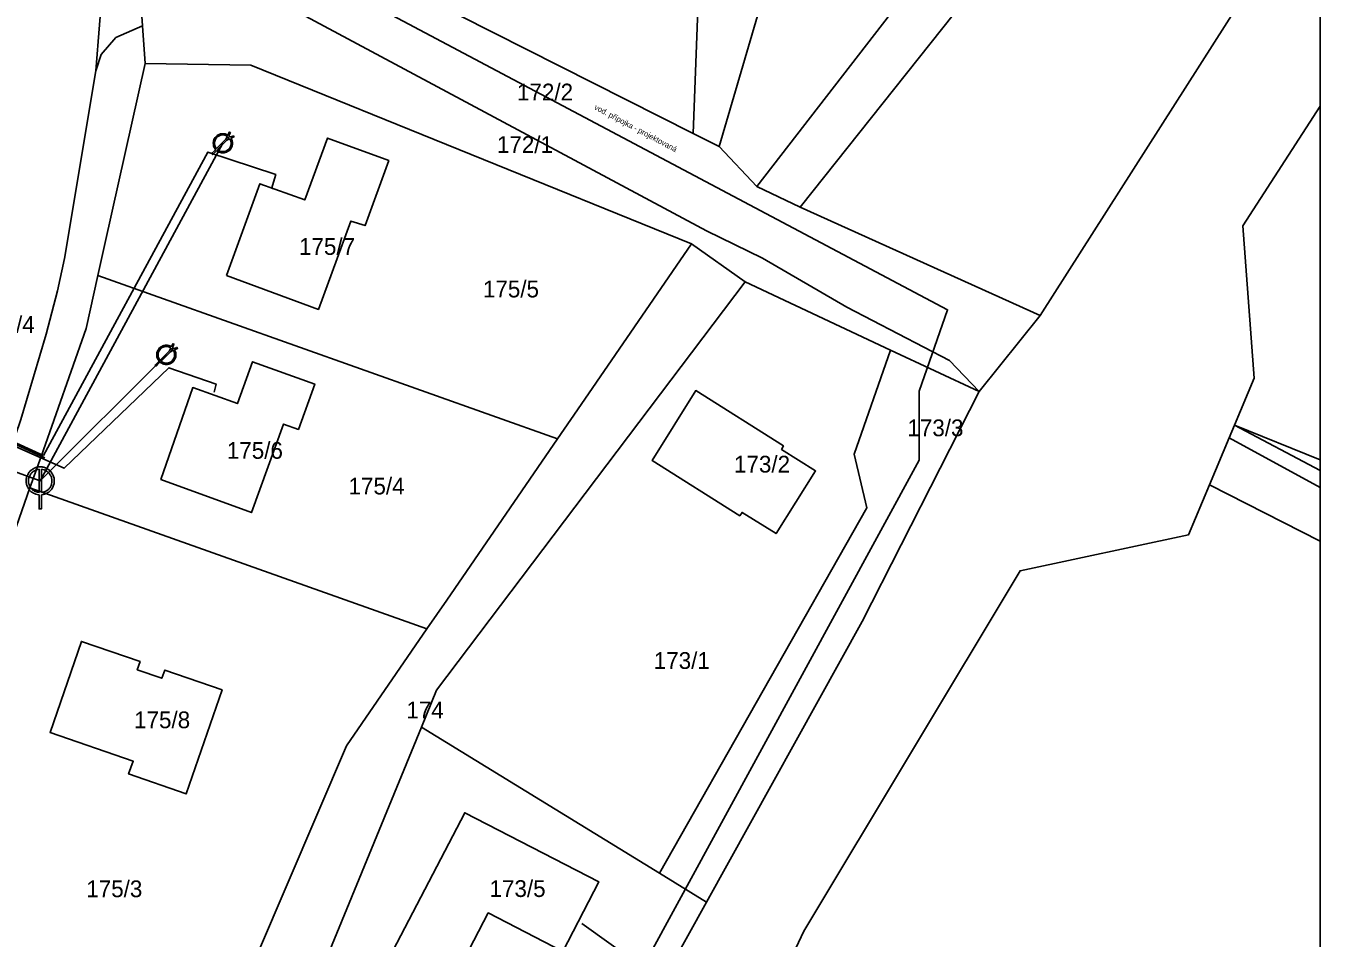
# Model space of a CAD drawing. Extents: x -559956 to -559707, y -1077221 to -1076919.
# Drawn here: x -559822.9 to -559707, y -1077119.6 to -1077037.9 of the extents above; entities that cross this region are included whole.
import ezdxf

# ---------------------------------------------------------------- set-up
doc = ezdxf.new("R2010")
doc.units = 0
for name, color, linetype in [('Chránička', 7, 'Continuous'), ('Doplňkový popis - vodovod', 7, 'Continuous'), ('Kanalizační přípojka', 7, 'Continuous'), ('Kanalizační šachta', 7, 'Continuous'), ('Odběrné místo na kanalizaci', 7, 'Continuous'), ('Parcela-polygon', 7, 'Continuous'), ('Parcela-text', 7, 'Continuous'), ('Vodovodní přípojka', 7, 'Continuous')]:
    doc.layers.add(name, color=color, linetype=linetype)

msp = doc.modelspace()

# ---------------------------------------------------------------- linework, layer by layer
at = {"layer": 'Chránička'}
msp.add_line((-559830.03, -1077072.56), (-559821.17, -1077076.58), dxfattribs=at)
at = {"layer": 'Kanalizační přípojka'}
msp.add_line((-559810.28, -1077067.37), (-559821.57, -1077078.65), dxfattribs=at)
msp.add_lwpolyline([(-559805.23, -1077048.44), (-559821.57, -1077078.65), (-559834.68, -1077073.91)], dxfattribs=at)
at = {"layer": 'Kanalizační šachta'}
for points in [[(-559821.67, -1077079.68), (-559821.67, -1077077.61)], [(-559821.47, -1077077.61), (-559821.47, -1077079.68)], [(-559821.47, -1077079.9), (-559821.47, -1077081.15), (-559821.67, -1077081.15), (-559821.67, -1077079.9)]]:
    msp.add_lwpolyline(points, dxfattribs=at)
for points in [[(-559821.67, -1077079.9), (-559821.93, -1077079.88), (-559822.19, -1077079.73), (-559822.49, -1077079.57), (-559822.65, -1077079.27), (-559822.82, -1077078.97), (-559822.82, -1077078.65), (-559822.82, -1077078.32), (-559822.65, -1077078.02), (-559822.48, -1077077.72), (-559822.18, -1077077.56), (-559821.89, -1077077.4), (-559821.57, -1077077.4), (-559821.25, -1077077.4), (-559820.95, -1077077.56), (-559820.66, -1077077.72), (-559820.49, -1077078.02), (-559820.32, -1077078.32), (-559820.32, -1077078.65), (-559820.32, -1077078.97), (-559820.48, -1077079.27), (-559820.65, -1077079.57), (-559820.95, -1077079.73), (-559821.21, -1077079.88), (-559821.47, -1077079.9)], [(-559821.67, -1077077.61), (-559821.87, -1077077.63), (-559822.08, -1077077.74), (-559822.33, -1077077.88), (-559822.47, -1077078.13), (-559822.61, -1077078.38), (-559822.61, -1077078.65), (-559822.61, -1077078.92), (-559822.47, -1077079.17), (-559822.34, -1077079.41), (-559822.09, -1077079.55), (-559821.88, -1077079.67), (-559821.67, -1077079.68)], [(-559821.47, -1077079.68), (-559821.26, -1077079.67), (-559821.05, -1077079.55), (-559820.8, -1077079.41), (-559820.66, -1077079.17), (-559820.53, -1077078.92), (-559820.53, -1077078.65), (-559820.53, -1077078.38), (-559820.67, -1077078.13), (-559820.81, -1077077.88), (-559821.06, -1077077.74), (-559821.27, -1077077.63), (-559821.47, -1077077.61)]]:
    msp.add_open_spline(points, degree=3, dxfattribs=at)
at = {"layer": 'Odběrné místo na kanalizaci'}
for points in [[(-559805.8, -1077048.91), (-559804.95, -1077048.07), (-559804.82, -1077047.81)], [(-559804.61, -1077048.03), (-559804.87, -1077048.16), (-559805.71, -1077049)], [(-559804.73, -1077047.88), (-559804.78, -1077047.98), (-559804.68, -1077047.93)], [(-559804.77, -1077047.71), (-559804.76, -1077047.69), (-559804.71, -1077047.58), (-559804.65, -1077047.44), (-559804.55, -1077047.48), (-559804.62, -1077047.64), (-559804.67, -1077047.76), (-559804.68, -1077047.78)], [(-559804.57, -1077047.88), (-559804.56, -1077047.87), (-559804.43, -1077047.83), (-559804.28, -1077047.77), (-559804.23, -1077047.86), (-559804.37, -1077047.92), (-559804.49, -1077047.97), (-559804.51, -1077047.98)], [(-559805.79, -1077049.08), (-559805.8, -1077049.1), (-559805.89, -1077049.19), (-559806.14, -1077049.44), (-559806.23, -1077049.35), (-559805.98, -1077049.1), (-559805.89, -1077049.01), (-559805.88, -1077049)], [(-559810.85, -1077067.85), (-559810.01, -1077067), (-559809.88, -1077066.75)], [(-559809.83, -1077066.65), (-559809.82, -1077066.63), (-559809.77, -1077066.51), (-559809.71, -1077066.37), (-559809.61, -1077066.41), (-559809.67, -1077066.58), (-559809.72, -1077066.7), (-559809.73, -1077066.71)], [(-559809.78, -1077066.82), (-559809.83, -1077066.92), (-559809.73, -1077066.87)], [(-559809.63, -1077066.82), (-559809.61, -1077066.81), (-559809.49, -1077066.76), (-559809.34, -1077066.7), (-559809.28, -1077066.79), (-559809.43, -1077066.85), (-559809.54, -1077066.9), (-559809.56, -1077066.91)], [(-559810.84, -1077068.02), (-559810.86, -1077068.03), (-559810.95, -1077068.12), (-559811.2, -1077068.37), (-559811.29, -1077068.28), (-559811.03, -1077068.03), (-559810.94, -1077067.94), (-559810.93, -1077067.93)], [(-559809.66, -1077066.96), (-559809.92, -1077067.09), (-559810.76, -1077067.94)]]:
    msp.add_lwpolyline(points, dxfattribs=at)
for points, degree in [([(-559805.88, -1077049), (-559805.93, -1077048.93), (-559805.97, -1077048.86), (-559806.08, -1077048.66), (-559806.08, -1077048.44), (-559806.08, -1077048.21), (-559805.97, -1077048.01), (-559805.85, -1077047.8), (-559805.65, -1077047.69), (-559805.44, -1077047.58), (-559805.23, -1077047.58), (-559805.01, -1077047.58), (-559804.81, -1077047.69), (-559804.79, -1077047.7), (-559804.77, -1077047.71)], 3), ([(-559804.82, -1077047.81), (-559804.84, -1077047.8), (-559804.86, -1077047.79), (-559805.04, -1077047.69), (-559805.23, -1077047.69), (-559805.42, -1077047.69), (-559805.59, -1077047.79), (-559805.77, -1077047.88), (-559805.87, -1077048.06), (-559805.97, -1077048.24), (-559805.97, -1077048.44), (-559805.97, -1077048.63), (-559805.87, -1077048.8), (-559805.84, -1077048.86), (-559805.8, -1077048.91)], 3), ([(-559804.51, -1077047.98), (-559804.5, -1077047.99), (-559804.49, -1077048.01), (-559804.37, -1077048.21), (-559804.37, -1077048.44), (-559804.37, -1077048.66), (-559804.49, -1077048.86), (-559804.6, -1077049.06), (-559804.8, -1077049.18), (-559805.01, -1077049.29), (-559805.23, -1077049.29), (-559805.45, -1077049.29), (-559805.65, -1077049.18), (-559805.73, -1077049.14), (-559805.79, -1077049.08)], 3), ([(-559805.71, -1077049), (-559805.66, -1077049.05), (-559805.6, -1077049.08), (-559805.42, -1077049.18), (-559805.23, -1077049.18), (-559805.04, -1077049.18), (-559804.86, -1077049.08), (-559804.68, -1077048.98), (-559804.58, -1077048.8), (-559804.49, -1077048.63), (-559804.49, -1077048.44), (-559804.49, -1077048.24), (-559804.58, -1077048.06), (-559804.6, -1077048.04), (-559804.61, -1077048.03)], 3), ([(-559804.68, -1077047.93), (-559804.7, -1077047.91), (-559804.73, -1077047.88)], 2), ([(-559804.68, -1077047.78), (-559804.62, -1077047.83), (-559804.57, -1077047.88)], 2), ([(-559810.93, -1077067.93), (-559810.98, -1077067.87), (-559811.02, -1077067.79), (-559811.14, -1077067.59), (-559811.14, -1077067.37), (-559811.14, -1077067.15), (-559811.02, -1077066.94), (-559810.91, -1077066.73), (-559810.7, -1077066.62), (-559810.5, -1077066.51), (-559810.28, -1077066.51), (-559810.07, -1077066.51), (-559809.86, -1077066.62), (-559809.84, -1077066.63), (-559809.83, -1077066.65)], 3), ([(-559809.88, -1077066.75), (-559809.9, -1077066.73), (-559809.92, -1077066.72), (-559810.1, -1077066.63), (-559810.28, -1077066.63), (-559810.47, -1077066.63), (-559810.65, -1077066.72), (-559810.83, -1077066.82), (-559810.93, -1077067), (-559811.02, -1077067.17), (-559811.02, -1077067.37), (-559811.02, -1077067.56), (-559810.93, -1077067.74), (-559810.89, -1077067.8), (-559810.85, -1077067.85)], 3), ([(-559809.73, -1077066.87), (-559809.76, -1077066.84), (-559809.78, -1077066.82)], 2), ([(-559809.73, -1077066.71), (-559809.68, -1077066.76), (-559809.63, -1077066.82)], 2), ([(-559809.56, -1077066.91), (-559809.55, -1077066.92), (-559809.54, -1077066.94), (-559809.43, -1077067.15), (-559809.43, -1077067.37), (-559809.43, -1077067.59), (-559809.54, -1077067.79), (-559809.65, -1077068), (-559809.86, -1077068.11), (-559810.06, -1077068.22), (-559810.28, -1077068.22), (-559810.5, -1077068.22), (-559810.71, -1077068.11), (-559810.78, -1077068.07), (-559810.84, -1077068.02)], 3), ([(-559810.76, -1077067.94), (-559810.71, -1077067.98), (-559810.65, -1077068.01), (-559810.47, -1077068.11), (-559810.28, -1077068.11), (-559810.09, -1077068.11), (-559809.91, -1077068.01), (-559809.74, -1077067.91), (-559809.64, -1077067.74), (-559809.54, -1077067.56), (-559809.54, -1077067.37), (-559809.54, -1077067.17), (-559809.64, -1077067), (-559809.65, -1077066.98), (-559809.66, -1077066.96)], 3)]:
    msp.add_open_spline(points, degree=degree, dxfattribs=at)
at = {"layer": 'Parcela-polygon'}
for p, q in [((-559707.02, -1077045.12), (-559707.02, -1077024.54)), ((-559707.02, -1077076.77), (-559707.02, -1077045.12)), ((-559707.02, -1077077.73), (-559707.02, -1077076.77)), ((-559707.02, -1077079.24), (-559707.02, -1077077.73)), ((-559707.02, -1077084.04), (-559707.02, -1077079.24)), ((-559707.02, -1077181.6), (-559707.02, -1077084.04))]:
    msp.add_line(p, q, dxfattribs=at)
for points in [[(-559823.32, -1077073.15), (-559821.04, -1077065.52), (-559820.03, -1077061.65), (-559819.41, -1077058.74), (-559816.6, -1077041.94), (-559815.93, -1077033.69), (-559817.92, -1077019.93), (-559819.43, -1077009.52), (-559820.21, -1077004.57), (-559821.27, -1076998.68), (-559822.96, -1076988.81)], [(-559707.02, -1076994.78), (-559711.14, -1076992.39), (-559741.39, -1077031.54), (-559757.43, -1077052.31), (-559753.56, -1077054.16), (-559707.02, -1076995.64)], [(-559707.02, -1076995.64), (-559753.56, -1077054.16), (-559732.09, -1077063.84), (-559707.02, -1077024.54)], [(-559707.02, -1077024.54), (-559732.09, -1077063.84), (-559737.55, -1077070.66), (-559748, -1077091.24), (-559761.93, -1077116.33), (-559776.08, -1077141.84), (-559781.47, -1077152.19), (-559794.21, -1077176.64), (-559804.13, -1077198.3), (-559804.99, -1077200.42), (-559813.55, -1077221.34)], [(-559841.22, -1077123.3), (-559834.22, -1077106.14), (-559825.6, -1077088.11), (-559822.49, -1077079.28), (-559821.5, -1077076.46), (-559817.47, -1077065.01), (-559816.41, -1077060.26), (-559815.75, -1077057.31), (-559812.17, -1077041.3), (-559812.41, -1077037.94), (-559814.79, -1077038.97), (-559816.13, -1077040.49), (-559816.6, -1077041.94), (-559819.41, -1077058.74), (-559820.03, -1077061.65), (-559821.04, -1077065.52), (-559823.32, -1077073.15), (-559826.24, -1077081.64), (-559828.56, -1077087.59), (-559836.17, -1077104.99), (-559841.38, -1077116.88), (-559843.69, -1077122.42)], [(-559801.67, -1077221.34), (-559800.59, -1077217.94), (-559792.07, -1077197.58), (-559790.13, -1077192.93), (-559770.77, -1077153.33), (-559769.65, -1077152.21), (-559766.54, -1077149.07), (-559762.33, -1077138.31), (-559753.22, -1077118.95), (-559733.87, -1077086.69), (-559718.8, -1077083.46), (-559716.92, -1077078.99), (-559715.17, -1077074.8), (-559714.69, -1077073.65), (-559712.93, -1077069.45), (-559713.95, -1077055.83), (-559707.02, -1077045.12)], [(-559707.02, -1077045.12), (-559713.95, -1077055.83), (-559712.93, -1077069.45), (-559714.69, -1077073.65), (-559707.02, -1077076.77)], [(-559707.02, -1077077.73), (-559714.69, -1077073.65), (-559715.17, -1077074.8), (-559707.02, -1077079.24)], [(-559707.02, -1077076.77), (-559714.69, -1077073.65), (-559707.02, -1077077.73)], [(-559707.02, -1077079.24), (-559715.17, -1077074.8), (-559716.92, -1077078.99), (-559707.02, -1077084.04)], [(-559707.02, -1077084.04), (-559716.92, -1077078.99), (-559718.8, -1077083.46), (-559733.87, -1077086.69), (-559753.22, -1077118.95), (-559762.33, -1077138.31), (-559766.54, -1077149.07), (-559769.65, -1077152.21), (-559707.02, -1077181.6)]]:
    msp.add_lwpolyline(points, dxfattribs=at)
for points in [[(-559772.81, -1077013.84), (-559787.01, -1077035.47), (-559763.12, -1077047.57), (-559762.08, -1077019.88)], [(-559815.93, -1077033.69), (-559816.6, -1077041.94), (-559816.13, -1077040.49), (-559814.79, -1077038.97), (-559812.41, -1077037.94), (-559813.04, -1077028.88), (-559813.27, -1077025.59), (-559814.85, -1077024.48), (-559816.36, -1077023.11), (-559817.45, -1077021.39), (-559817.92, -1077019.93)], [(-559763.12, -1077047.57), (-559760.82, -1077048.73), (-559753.73, -1077024.58), (-559762.08, -1077019.88)], [(-559787.01, -1077035.47), (-559809.39, -1077024.33), (-559810.22, -1077023.06), (-559813.57, -1077021.42), (-559813.27, -1077025.59), (-559813.04, -1077028.88), (-559761.95, -1077056.26), (-559756.94, -1077058.73), (-559749.38, -1077063.1), (-559740.18, -1077067.86), (-559737.55, -1077070.66), (-559732.09, -1077063.84), (-559753.56, -1077054.16), (-559757.43, -1077052.31), (-559760.82, -1077048.73), (-559763.12, -1077047.57)], [(-559753.73, -1077024.58), (-559760.82, -1077048.73), (-559757.43, -1077052.31), (-559741.39, -1077031.54)], [(-559737.55, -1077070.66), (-559740.18, -1077067.86), (-559749.38, -1077063.1), (-559756.94, -1077058.73), (-559761.95, -1077056.26), (-559813.04, -1077028.88), (-559812.41, -1077037.94), (-559812.17, -1077041.3), (-559802.73, -1077041.45), (-559763.29, -1077057.42), (-559758.48, -1077060.82), (-559745.46, -1077066.94)], [(-559812.17, -1077041.3), (-559815.75, -1077057.31), (-559816.41, -1077060.26), (-559775.27, -1077074.87), (-559773.5, -1077072.29), (-559763.29, -1077057.42), (-559802.73, -1077041.45)], [(-559804.89, -1077060.26), (-559801.92, -1077052.05), (-559797.9, -1077053.51), (-559795.86, -1077047.97), (-559790.38, -1077049.98), (-559792.5, -1077055.8), (-559793.76, -1077055.4), (-559796.67, -1077063.3)], [(-559804.89, -1077060.26), (-559796.67, -1077063.3), (-559793.76, -1077055.4), (-559792.5, -1077055.8), (-559790.38, -1077049.98), (-559795.86, -1077047.97), (-559797.9, -1077053.51), (-559801.92, -1077052.05)], [(-559786.1, -1077097.37), (-559758.48, -1077060.82), (-559763.29, -1077057.42), (-559773.5, -1077072.29), (-559775.27, -1077074.87), (-559785.19, -1077089.31), (-559786.96, -1077091.88), (-559794.15, -1077102.35), (-559802.04, -1077120.75), (-559808.49, -1077127.23), (-559816.84, -1077129.72), (-559838.86, -1077123.92), (-559841.22, -1077123.3), (-559843.27, -1077128.31), (-559815.3, -1077135.92), (-559806.38, -1077134), (-559797.01, -1077123.99), (-559787.45, -1077100.67)], [(-559817.47, -1077065.01), (-559821.5, -1077076.46), (-559822.49, -1077079.28), (-559786.96, -1077091.88), (-559785.19, -1077089.31), (-559775.27, -1077074.87), (-559816.41, -1077060.26)], [(-559766.16, -1077113.76), (-559747.59, -1077081.07), (-559748.72, -1077076.27), (-559745.46, -1077066.94), (-559758.48, -1077060.82), (-559786.1, -1077097.37), (-559787.45, -1077100.67)], [(-559802.58, -1077067.98), (-559803.93, -1077071.73), (-559807.92, -1077070.3), (-559810.77, -1077078.51), (-559802.67, -1077081.48), (-559799.8, -1077073.57), (-559798.46, -1077074.04), (-559797, -1077069.99)], [(-559798.46, -1077074.04), (-559799.8, -1077073.57), (-559802.67, -1077081.48), (-559810.77, -1077078.51), (-559807.92, -1077070.3), (-559803.93, -1077071.73), (-559802.58, -1077067.98), (-559797, -1077069.99)], [(-559737.55, -1077070.66), (-559745.46, -1077066.94), (-559748.72, -1077076.27), (-559747.59, -1077081.07), (-559766.16, -1077113.76), (-559761.93, -1077116.33), (-559748, -1077091.24)], [(-559762.9, -1077070.57), (-559755.06, -1077075.51), (-559755.22, -1077075.83), (-559752.18, -1077077.75), (-559755.71, -1077083.36), (-559758.76, -1077081.47), (-559758.96, -1077081.77), (-559766.81, -1077076.82)], [(-559766.81, -1077076.82), (-559758.96, -1077081.77), (-559758.76, -1077081.47), (-559755.71, -1077083.36), (-559752.18, -1077077.75), (-559755.22, -1077075.83), (-559755.06, -1077075.51), (-559762.9, -1077070.57)], [(-559786.96, -1077091.88), (-559822.49, -1077079.28), (-559825.6, -1077088.11), (-559834.22, -1077106.14), (-559841.22, -1077123.3), (-559838.86, -1077123.92), (-559816.84, -1077129.72), (-559808.49, -1077127.23), (-559802.04, -1077120.75), (-559794.15, -1077102.35)], [(-559805.29, -1077097.35), (-559808.51, -1077106.66), (-559813.67, -1077104.87), (-559813.25, -1077103.74), (-559820.69, -1077101.17), (-559817.88, -1077093.01), (-559812.64, -1077094.82), (-559812.89, -1077095.55), (-559810.69, -1077096.31), (-559810.42, -1077095.58)], [(-559810.69, -1077096.31), (-559812.89, -1077095.55), (-559812.64, -1077094.82), (-559817.88, -1077093.01), (-559820.69, -1077101.17), (-559813.25, -1077103.74), (-559813.67, -1077104.87), (-559808.51, -1077106.66), (-559805.29, -1077097.35), (-559810.42, -1077095.58)], [(-559766.16, -1077113.76), (-559787.45, -1077100.67), (-559797.01, -1077123.99), (-559806.38, -1077134), (-559815.3, -1077135.92), (-559776.08, -1077141.84), (-559761.93, -1077116.33)], [(-559791.08, -1077122.77), (-559785.75, -1077125.53), (-559781.47, -1077117.31), (-559774.81, -1077120.76), (-559771.59, -1077114.52), (-559783.58, -1077108.34)], [(-559771.59, -1077114.52), (-559774.81, -1077120.76), (-559781.47, -1077117.31), (-559785.75, -1077125.53), (-559791.08, -1077122.77), (-559783.58, -1077108.34)]]:
    msp.add_lwpolyline(points, close=True, dxfattribs=at)
at = {"layer": 'Vodovodní přípojka'}
msp.add_line((-559821.29, -1077076.37), (-559830.24, -1077072.32), dxfattribs=at)
for points in [[(-559812.21, -1077025.22), (-559740.37, -1077063.33), (-559742.92, -1077070.61), (-559742.92, -1077076.8), (-559767.64, -1077122.16), (-559773.1, -1077118.25)], [(-559800.86, -1077052.52), (-559800.49, -1077051.24), (-559806.56, -1077049.22), (-559821.29, -1077076.37)], [(-559806.01, -1077070.72), (-559805.83, -1077069.99), (-559810.05, -1077068.52), (-559819.43, -1077077.52), (-559830.35, -1077072.67)]]:
    msp.add_lwpolyline(points, dxfattribs=at)

# ---------------------------------------------------------------- texts
at = {"layer": 'Doplňkový popis - vodovod'}
msp.add_text('vod. přípojka - projektovaná', height=0.5, rotation=332.058, dxfattribs=at).set_placement((-559772.03, -1077045.37))
at = {"layer": 'Parcela-text'}
for s, p in [('172/2', (-559778.9, -1077044.6)), ('172/1', (-559780.7, -1077049.3)), ('175/7', (-559798.41, -1077058.42)), ('175/5', (-559781.95, -1077062.23)), ('1892/4', (-559828.2, -1077065.4)), ('173/3', (-559743.96, -1077074.65)), ('175/6', (-559804.87, -1077076.67)), ('173/2', (-559759.48, -1077077.9)), ('175/4', (-559793.98, -1077079.86)), ('173/1', (-559766.66, -1077095.47)), ('175/8', (-559813.17, -1077100.78)), ('174', (-559788.8, -1077099.9)), ('175/3', (-559817.45, -1077115.9)), ('173/5', (-559781.36, -1077115.88))]:
    msp.add_text(s, height=1.5, dxfattribs=at).set_placement(p)

doc.saveas('drawing.dxf')
